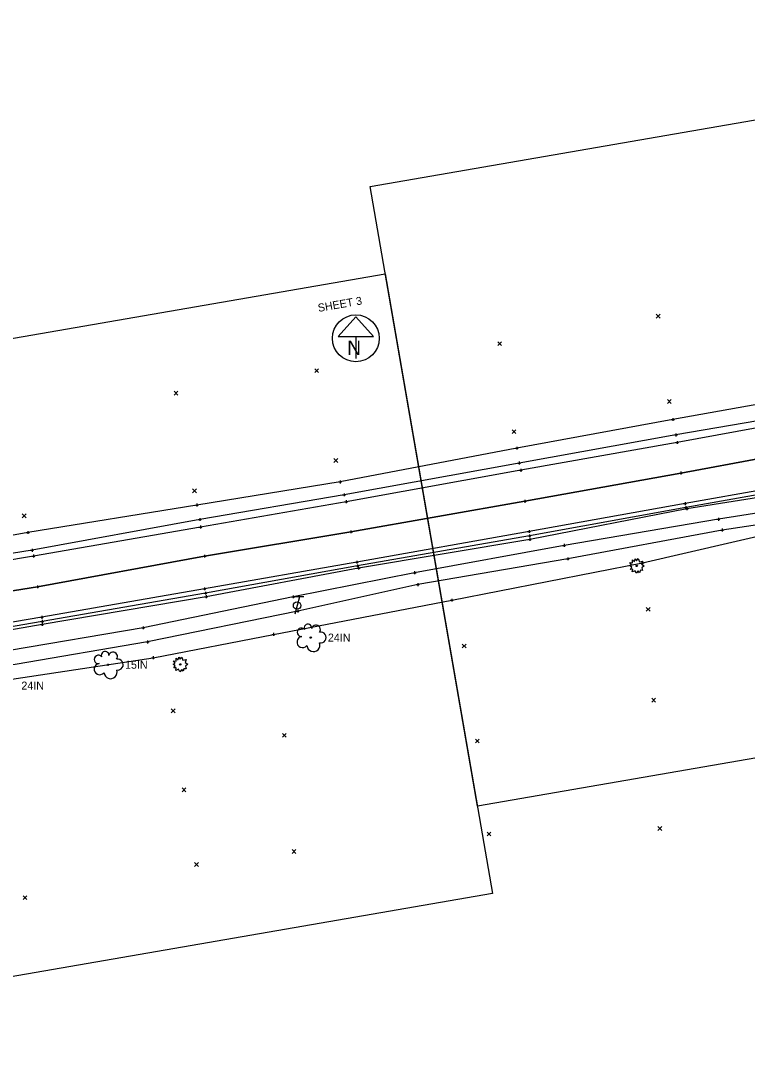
# Model space of a CAD drawing. Extents: x 1386013 to 1389776, y 604170 to 607009.
# Drawn here: x 1387227.5 to 1387481.7, y 604613.9 to 604977.2 of the extents above; entities that cross this region are included whole.
import ezdxf

# ---------------------------------------------------------------- set-up
doc = ezdxf.new("R2010")
doc.units = 0
for name, color, linetype in [('_CIVIL_CONSTRUCTION', 7, 'Continuous'), ('DV_X_Text', 7, 'Continuous'), ('PM_X_CL_Double_Solid', 7, 'Continuous'), ('PV_X_COP', 7, 'Continuous'), ('PV_X_EOP', 7, 'Continuous'), ('PV_X_Shoulder', 7, 'Continuous'), ('SH_Cut_Line', 7, 'Continuous'), ('SH_Masking', 7, 'Continuous'), ('SH_Text', 7, 'Continuous'), ('SV_X_Random_Point', 7, 'Continuous'), ('SV_X_Toe_of_Slope', 7, 'Continuous'), ('SV_X_Top_of_Bank', 7, 'Continuous'), ('UT_X_Telecom_Cells', 7, 'Continuous'), ('VG_X_Text', 7, 'Continuous')]:
    doc.layers.add(name, color=color, linetype=linetype)

msp = doc.modelspace()

# ---------------------------------------------------------------- linework, layer by layer
at = {"layer": '_CIVIL_CONSTRUCTION'}
for points in [[(1387442.96, 604788.25), (1387443.57, 604788.99), (1387443.98, 604787.93), (1387445.08, 604788.11), (1387444.74, 604787.1), (1387445.68, 604786.51), (1387444.83, 604785.77), (1387445.08, 604784.86), (1387444.32, 604784.93), (1387444, 604784.01), (1387443.57, 604784.71), (1387442.89, 604783.89), (1387442.46, 604784.78), (1387441.44, 604784.35), (1387441.63, 604785.29), (1387440.82, 604785.2), (1387441.3, 604785.99), (1387440.53, 604786.56), (1387441.27, 604786.83), (1387440.66, 604787.63), (1387441.59, 604787.52), (1387441.56, 604788.56), (1387442.31, 604787.99), (1387442.52, 604788.97), (1387442.96, 604788.25)], [(1387283.25, 604753.81), (1387283.85, 604754.55), (1387284.27, 604753.49), (1387285.36, 604753.67), (1387285.02, 604752.66), (1387285.97, 604752.07), (1387285.11, 604751.33), (1387285.36, 604750.42), (1387284.61, 604750.49), (1387284.28, 604749.57), (1387283.85, 604750.26), (1387283.18, 604749.45), (1387282.75, 604750.33), (1387281.73, 604749.9), (1387281.92, 604750.85), (1387281.11, 604750.76), (1387281.58, 604751.55), (1387280.81, 604752.12), (1387281.55, 604752.38), (1387280.94, 604753.19), (1387281.88, 604753.08), (1387281.85, 604754.12), (1387282.6, 604753.55), (1387282.81, 604754.53), (1387283.25, 604753.81)]]:
    msp.add_lwpolyline(points, dxfattribs=at)
for centre, radius in [((1387443.05, 604786.44), 0.23), ((1387328.98, 604761.37), 0.24), ((1387257.99, 604751.88), 0.24), ((1387283.33, 604752), 0.23)]:
    msp.add_circle(centre, radius, dxfattribs=at)
for centre, radius, start, end in [((1387327.99, 604764.73), 1.32, 354.0047, 205.9741), ((1387325.67, 604763.23), 1.47, 39.0625, 279.5412), ((1387330.8, 604764.19), 1.55, 323.83, 165.0376), ((1387332.44, 604761.4), 1.91, 259.1453, 101.4596), ((1387326.12, 604759.82), 1.97, 96.1722, 320.5737), ((1387329.92, 604758.76), 2.28, 184.9476, 19.4572), ((1387254.68, 604753.74), 1.47, 39.0625, 279.5412), ((1387257, 604755.25), 1.32, 354.0047, 205.9741), ((1387259.81, 604754.71), 1.55, 323.83, 165.0376), ((1387255.13, 604750.33), 1.97, 96.1722, 320.5737), ((1387261.45, 604751.92), 1.91, 259.1453, 101.4596), ((1387258.93, 604749.27), 2.28, 184.9476, 19.4572)]:
    msp.add_arc(centre, radius, start, end, dxfattribs=at)
at = {"layer": 'DV_X_Text'}
for p, q in [((1387455.23, 604837.69), (1387456.23, 604837.69)), ((1387455.73, 604838.19), (1387455.73, 604837.19)), ((1387455.73, 604837.69), (1387455.73, 604837.69)), ((1387456.28, 604832.26), (1387457.28, 604832.26)), ((1387456.78, 604832.76), (1387456.78, 604831.76)), ((1387456.78, 604832.26), (1387456.78, 604832.26)), ((1387401.04, 604828.15), (1387401.04, 604827.15)), ((1387456.67, 604829.65), (1387457.67, 604829.65)), ((1387457.17, 604830.15), (1387457.17, 604829.15)), ((1387457.17, 604829.65), (1387457.17, 604829.65)), ((1387400.54, 604827.65), (1387401.54, 604827.65)), ((1387401.04, 604827.65), (1387401.04, 604827.65)), ((1387401.41, 604822.43), (1387402.41, 604822.43)), ((1387401.91, 604822.93), (1387401.91, 604821.93)), ((1387401.91, 604822.43), (1387401.91, 604822.43)), ((1387401.94, 604819.9), (1387402.94, 604819.9)), ((1387402.44, 604820.4), (1387402.44, 604819.4)), ((1387402.44, 604819.9), (1387402.44, 604819.9)), ((1387457.99, 604818.93), (1387458.99, 604818.93)), ((1387458.49, 604819.43), (1387458.49, 604818.43)), ((1387458.49, 604818.93), (1387458.49, 604818.93)), ((1387338.79, 604815.83), (1387339.79, 604815.83)), ((1387339.29, 604816.33), (1387339.29, 604815.33)), ((1387339.29, 604815.83), (1387339.29, 604815.83)), ((1387340.13, 604811.34), (1387341.13, 604811.34)), ((1387340.63, 604811.84), (1387340.63, 604810.84)), ((1387340.63, 604811.34), (1387340.63, 604811.34)), ((1387403.9, 604809.55), (1387403.9, 604808.55)), ((1387288.6, 604807.74), (1387289.6, 604807.74)), ((1387289.1, 604808.24), (1387289.1, 604807.24)), ((1387289.1, 604807.74), (1387289.1, 604807.74)), ((1387340.88, 604808.9), (1387341.88, 604808.9)), ((1387341.38, 604809.4), (1387341.38, 604808.4)), ((1387341.38, 604808.9), (1387341.38, 604808.9)), ((1387403.4, 604809.05), (1387404.4, 604809.05)), ((1387403.9, 604809.05), (1387403.9, 604809.05)), ((1387459.46, 604808.24), (1387460.46, 604808.24)), ((1387459.76, 604806.85), (1387460.76, 604806.85)), ((1387459.96, 604808.74), (1387459.96, 604807.74)), ((1387459.96, 604808.24), (1387459.96, 604808.24)), ((1387460.03, 604806.4), (1387461.03, 604806.4)), ((1387460.26, 604807.35), (1387460.26, 604806.35)), ((1387460.26, 604806.85), (1387460.26, 604806.85)), ((1387460.53, 604806.9), (1387460.53, 604805.9)), ((1387460.53, 604806.4), (1387460.53, 604806.4)), ((1387289.61, 604802.67), (1387290.61, 604802.67)), ((1387290.11, 604803.17), (1387290.11, 604802.17)), ((1387290.11, 604802.67), (1387290.11, 604802.67)), ((1387471.12, 604802.75), (1387472.12, 604802.75)), ((1387471.62, 604803.25), (1387471.62, 604802.25)), ((1387471.62, 604802.75), (1387471.62, 604802.75)), ((1387230.03, 604798.65), (1387230.03, 604797.65)), ((1387289.86, 604800.04), (1387290.86, 604800.04)), ((1387290.36, 604800.54), (1387290.36, 604799.54)), ((1387290.36, 604800.04), (1387290.36, 604800.04)), ((1387343.04, 604798.89), (1387343.04, 604797.89)), ((1387405.36, 604799), (1387405.36, 604798)), ((1387472.4, 604799.01), (1387473.4, 604799.01)), ((1387472.9, 604799.51), (1387472.9, 604798.51)), ((1387472.9, 604799.01), (1387472.9, 604799.01)), ((1387229.53, 604798.15), (1387230.53, 604798.15)), ((1387230.03, 604798.15), (1387230.03, 604798.15)), ((1387342.54, 604798.39), (1387343.54, 604798.39)), ((1387343.04, 604798.39), (1387343.04, 604798.39)), ((1387404.86, 604798.5), (1387405.86, 604798.5)), ((1387405.01, 604796.97), (1387406.01, 604796.97)), ((1387405.15, 604795.75), (1387406.15, 604795.75)), ((1387405.36, 604798.5), (1387405.36, 604798.5)), ((1387405.51, 604797.47), (1387405.51, 604796.47)), ((1387405.51, 604796.97), (1387405.51, 604796.97)), ((1387405.65, 604796.25), (1387405.65, 604795.25)), ((1387405.65, 604795.75), (1387405.65, 604795.75)), ((1387230.95, 604791.93), (1387231.95, 604791.93)), ((1387231.45, 604792.43), (1387231.45, 604791.43)), ((1387231.45, 604791.93), (1387231.45, 604791.93)), ((1387417.17, 604793.63), (1387418.17, 604793.63)), ((1387417.67, 604794.13), (1387417.67, 604793.13)), ((1387417.67, 604793.63), (1387417.67, 604793.63)), ((1387231.48, 604789.91), (1387232.48, 604789.91)), ((1387231.98, 604790.41), (1387231.98, 604789.41)), ((1387231.98, 604789.91), (1387231.98, 604789.91)), ((1387291.35, 604789.88), (1387292.35, 604789.88)), ((1387291.85, 604790.38), (1387291.85, 604789.38)), ((1387291.85, 604789.88), (1387291.85, 604789.88)), ((1387344.61, 604787.75), (1387345.61, 604787.75)), ((1387345.11, 604788.25), (1387345.11, 604787.25)), ((1387345.11, 604787.75), (1387345.11, 604787.75)), ((1387418.4, 604788.91), (1387419.4, 604788.91)), ((1387418.9, 604789.41), (1387418.9, 604788.41)), ((1387418.9, 604788.91), (1387418.9, 604788.91)), ((1387445.09, 604788.08), (1387445.09, 604787.08)), ((1387344.82, 604786.5), (1387345.82, 604786.5)), ((1387345.23, 604785.65), (1387346.23, 604785.65)), ((1387345.32, 604787), (1387345.32, 604786)), ((1387345.32, 604786.5), (1387345.32, 604786.5)), ((1387345.73, 604786.15), (1387345.73, 604785.15)), ((1387345.73, 604785.65), (1387345.73, 604785.65)), ((1387365.33, 604784.57), (1387365.33, 604783.57)), ((1387444.59, 604787.58), (1387445.59, 604787.58)), ((1387445.09, 604787.58), (1387445.09, 604787.58)), ((1387364.83, 604784.07), (1387365.83, 604784.07)), ((1387365.33, 604784.07), (1387365.33, 604784.07)), ((1387232.81, 604779.13), (1387233.81, 604779.13)), ((1387233.31, 604779.63), (1387233.31, 604778.63)), ((1387233.31, 604779.13), (1387233.31, 604779.13)), ((1387291.3, 604778.43), (1387292.3, 604778.43)), ((1387291.64, 604776.93), (1387292.64, 604776.93)), ((1387291.8, 604778.93), (1387291.8, 604777.93)), ((1387291.8, 604778.43), (1387291.8, 604778.43)), ((1387292.14, 604777.43), (1387292.14, 604776.43)), ((1387292.14, 604776.93), (1387292.14, 604776.93)), ((1387365.91, 604779.89), (1387366.91, 604779.89)), ((1387366.41, 604780.39), (1387366.41, 604779.39)), ((1387366.41, 604779.89), (1387366.41, 604779.89)), ((1387291.9, 604775.68), (1387292.9, 604775.68)), ((1387292.4, 604776.18), (1387292.4, 604775.18)), ((1387292.4, 604775.68), (1387292.4, 604775.68)), ((1387322.35, 604775.64), (1387323.35, 604775.64)), ((1387322.85, 604776.14), (1387322.85, 604775.14)), ((1387322.85, 604775.64), (1387322.85, 604775.64)), ((1387377.79, 604774.45), (1387378.79, 604774.45)), ((1387378.29, 604774.95), (1387378.29, 604773.95)), ((1387378.29, 604774.45), (1387378.29, 604774.45)), ((1387323.97, 604770.63), (1387324.97, 604770.63)), ((1387324.47, 604771.13), (1387324.47, 604770.13)), ((1387324.47, 604770.63), (1387324.47, 604770.63)), ((1387234.36, 604768.47), (1387235.36, 604768.47)), ((1387234.5, 604765.96), (1387235.5, 604765.96)), ((1387234.54, 604767.03), (1387235.54, 604767.03)), ((1387234.86, 604768.97), (1387234.86, 604767.97)), ((1387234.86, 604768.47), (1387234.86, 604768.47)), ((1387235, 604766.46), (1387235, 604765.46)), ((1387235, 604765.96), (1387235, 604765.96)), ((1387235.04, 604767.53), (1387235.04, 604766.53)), ((1387235.04, 604767.03), (1387235.04, 604767.03)), ((1387269.83, 604764.8), (1387270.83, 604764.8)), ((1387270.33, 604765.3), (1387270.33, 604764.3)), ((1387270.33, 604764.8), (1387270.33, 604764.8)), ((1387315.4, 604762.49), (1387316.4, 604762.49)), ((1387315.9, 604762.99), (1387315.9, 604761.99)), ((1387315.9, 604762.49), (1387315.9, 604762.49)), ((1387271.39, 604759.84), (1387272.39, 604759.84)), ((1387271.89, 604760.34), (1387271.89, 604759.34)), ((1387271.89, 604759.84), (1387271.89, 604759.84)), ((1387273.3, 604754.33), (1387274.3, 604754.33)), ((1387273.8, 604754.83), (1387273.8, 604753.83)), ((1387273.8, 604754.33), (1387273.8, 604754.33))]:
    msp.add_line(p, q, dxfattribs=at)
at = {"layer": 'PM_X_CL_Double_Solid'}
msp.add_lwpolyline([(1386941.92, 604730.57), (1387000.37, 604739.9), (1387059.38, 604750.41), (1387127.32, 604761.93), (1387175.52, 604769.9), (1387233.31, 604779.13), (1387291.85, 604789.88), (1387343.04, 604798.39), (1387403.9, 604809.05), (1387458.49, 604818.93), (1387516.12, 604829.58), (1387574.82, 604839.73), (1387636.99, 604851.11), (1387704.35, 604863.01), (1387787.5, 604877.74), (1387859.73, 604890.76), (1387934.47, 604903.86), (1387998.85, 604914.97), (1388072.27, 604927.44)], dxfattribs=at)
at = {"layer": 'PV_X_COP'}
msp.add_lwpolyline([(1388072.27, 604927.44), (1387998.85, 604914.97), (1387934.47, 604903.86), (1387859.73, 604890.76), (1387787.5, 604877.74), (1387704.35, 604863.01), (1387636.99, 604851.11), (1387574.82, 604839.73), (1387516.12, 604829.58), (1387458.49, 604818.93), (1387403.9, 604809.05), (1387343.04, 604798.39), (1387291.85, 604789.88), (1387233.31, 604779.13), (1387175.52, 604769.9), (1387127.32, 604761.93), (1387059.38, 604750.41), (1387000.37, 604739.9), (1386941.92, 604730.57)], dxfattribs=at)
at = {"layer": 'PV_X_EOP'}
for points in [[(1388070.9, 604937.92), (1387997.67, 604925.46), (1387932.45, 604914.15), (1387857.85, 604900.92), (1387785.1, 604888.09), (1387704.04, 604873.65), (1387634.94, 604861.37), (1387573.23, 604850.33), (1387514.48, 604840.1), (1387457.17, 604829.65), (1387402.44, 604819.9), (1387341.38, 604808.9), (1387290.36, 604800.04), (1387231.98, 604789.91), (1387174.35, 604780.15), (1387125.76, 604771.91), (1387057.82, 604760.3), (1386999.09, 604750.97), (1386941.41, 604741.04)], [(1388073.48, 604916.74), (1388000.2, 604904.18), (1387936.61, 604893.17), (1387861, 604879.89), (1387788.15, 604866.91), (1387706.18, 604852.38), (1387637.62, 604840.16), (1387577.04, 604829.26), (1387518.08, 604818.58), (1387459.96, 604808.24), (1387405.36, 604798.5), (1387345.11, 604787.75), (1387291.8, 604778.43), (1387234.86, 604768.47), (1387177.43, 604758.7), (1387129.4, 604750.56), (1387061.72, 604739.2), (1387002.9, 604729.17), (1386943.42, 604719.4)]]:
    msp.add_lwpolyline(points, dxfattribs=at)
at = {"layer": 'PV_X_Shoulder'}
for points in [[(1388070.88, 604939.75), (1387997.08, 604927.24), (1387932.1, 604916.23), (1387857.34, 604902.99), (1387785.16, 604890.04), (1387703.39, 604875.43), (1387634.35, 604863.66), (1387572.42, 604852.64), (1387514.1, 604842.11), (1387456.78, 604832.26), (1387401.91, 604822.43), (1387340.63, 604811.34), (1387290.11, 604802.67), (1387231.45, 604791.93), (1387174.18, 604782.71), (1387125.33, 604774.1), (1387057.54, 604762.26), (1386998.59, 604752.7), (1386940.97, 604743.32)], [(1388073.66, 604915.38), (1388000.63, 604902.69), (1387936.79, 604891.84), (1387860.98, 604878.42), (1387788.19, 604865.06), (1387706.38, 604850.4), (1387637.88, 604838.5), (1387577.02, 604827.53), (1387518.12, 604817.16), (1387460.26, 604806.85), (1387405.51, 604796.97), (1387345.32, 604786.5), (1387292.14, 604776.93), (1387235.04, 604767.03), (1387177.5, 604757.13), (1387129.28, 604748.59), (1387117.65, 604744.89), (1387099.29, 604741.91), (1387094.7, 604743.05), (1387062.03, 604737.87), (1387002.75, 604727.47), (1386990.61, 604725.25), (1386985.4, 604722.84), (1386965.11, 604719.46)]]:
    msp.add_lwpolyline(points, dxfattribs=at)
at = {"layer": 'SH_Cut_Line'}
for points in [[(1387387.31, 604702.37), (1387349.76, 604919.15), (1387684.77, 604977.18), (1387722.32, 604760.41)], [(1387057.58, 604613.85), (1387020.03, 604830.63), (1387355.04, 604888.66), (1387392.59, 604671.89)]]:
    msp.add_lwpolyline(points, close=True, dxfattribs=at)
at = {"layer": 'SH_Masking'}
msp.add_circle((1387344.77, 604866.09), 8.2, dxfattribs=at)
at = {"layer": 'SH_Text'}
for p, q in [((1387344.77, 604873.57), (1387338.62, 604866.74)), ((1387350.93, 604866.74), (1387344.77, 604873.57)), ((1387338.62, 604866.74), (1387350.93, 604866.74)), ((1387344.77, 604866.74), (1387344.77, 604859.01))]:
    msp.add_line(p, q, dxfattribs=at)
msp.add_circle((1387344.77, 604866.09), 8.2, dxfattribs=at)
at = {"layer": 'SV_X_Random_Point'}
for p, q in [((1387449.88, 604873.17), (1387451.21, 604874.5)), ((1387449.88, 604874.5), (1387451.21, 604873.17)), ((1387394.45, 604863.52), (1387395.78, 604864.85)), ((1387394.45, 604864.85), (1387395.78, 604863.52)), ((1387330.37, 604854.08), (1387331.7, 604855.41)), ((1387330.37, 604855.41), (1387331.7, 604854.08)), ((1387281.13, 604846.22), (1387282.46, 604847.55)), ((1387281.13, 604847.55), (1387282.46, 604846.22)), ((1387453.81, 604843.29), (1387455.15, 604844.63)), ((1387453.81, 604844.63), (1387455.15, 604843.29)), ((1387399.45, 604832.74), (1387400.78, 604834.08)), ((1387399.45, 604834.08), (1387400.78, 604832.74)), ((1387337.1, 604822.67), (1387338.43, 604824)), ((1387337.1, 604824), (1387338.43, 604822.67)), ((1387287.61, 604812.06), (1387288.94, 604813.4)), ((1387287.61, 604813.4), (1387288.94, 604812.06)), ((1387228.04, 604803.3), (1387229.37, 604804.64)), ((1387228.04, 604804.64), (1387229.37, 604803.3)), ((1387446.4, 604770.59), (1387447.74, 604771.93)), ((1387446.4, 604771.93), (1387447.74, 604770.59)), ((1387382.01, 604757.78), (1387383.35, 604759.12)), ((1387382.01, 604759.12), (1387383.35, 604757.78)), ((1387448.31, 604738.8), (1387449.64, 604740.13)), ((1387448.31, 604740.13), (1387449.64, 604738.8)), ((1387280.19, 604735.05), (1387281.52, 604736.39)), ((1387280.19, 604736.39), (1387281.52, 604735.05)), ((1387319.04, 604726.54), (1387320.37, 604727.87)), ((1387319.04, 604727.87), (1387320.37, 604726.54)), ((1387386.57, 604724.53), (1387387.9, 604725.86)), ((1387386.57, 604725.86), (1387387.9, 604724.53)), ((1387283.94, 604707.46), (1387285.27, 604708.8)), ((1387283.94, 604708.8), (1387285.27, 604707.46)), ((1387390.69, 604692), (1387392.03, 604693.33)), ((1387390.69, 604693.33), (1387392.03, 604692)), ((1387450.48, 604693.9), (1387451.81, 604695.23)), ((1387450.48, 604695.23), (1387451.81, 604693.9)), ((1387322.43, 604685.84), (1387323.76, 604687.18)), ((1387322.43, 604687.18), (1387323.76, 604685.84)), ((1387288.35, 604681.33), (1387289.69, 604682.66)), ((1387288.35, 604682.66), (1387289.69, 604681.33)), ((1387228.32, 604669.75), (1387229.65, 604671.08)), ((1387228.32, 604671.08), (1387229.65, 604669.75))]:
    msp.add_line(p, q, dxfattribs=at)
at = {"layer": 'SV_X_Toe_of_Slope'}
for points in [[(1387571.9, 604860.13), (1387513.17, 604847.9), (1387455.73, 604837.69), (1387401.04, 604827.65), (1387339.29, 604815.83), (1387289.1, 604807.74), (1387230.03, 604798.15), (1387173.08, 604787.71), (1387123.84, 604780.19), (1387058.58, 604768.72), (1386997.09, 604757.11), (1386939.93, 604748.73), (1386883.98, 604739), (1386826.09, 604728.82), (1386769.04, 604719.03), (1386711.7, 604710.77), (1386654.03, 604700.72), (1386592.6, 604690.63), (1386534.1, 604681.18), (1386480.03, 604672.89), (1386465.51, 604671.66), (1386391.46, 604656.56), (1386330.8, 604647.36), (1386266.18, 604637.16)], [(1387642.64, 604832.21), (1387598.48, 604823.3), (1387558.95, 604817.37), (1387510.99, 604808.94), (1387471.62, 604802.75), (1387417.67, 604793.63), (1387365.33, 604784.07), (1387322.85, 604775.64), (1387270.33, 604764.8), (1387223.53, 604756.91), (1387181.6, 604750.67), (1387155.52, 604744), (1387129.15, 604740.81), (1387125.03, 604741.78), (1387120.43, 604741.02)], [(1387645.49, 604830.06), (1387640.63, 604828.81), (1387599.43, 604819.65), (1387560.44, 604813.11), (1387511.64, 604804.79), (1387472.9, 604799.01), (1387418.9, 604788.91), (1387366.41, 604779.89), (1387324.47, 604770.63), (1387271.89, 604759.84), (1387225.55, 604751.97), (1387182.66, 604746.29), (1387156.28, 604739.69), (1387120.85, 604736.53)]]:
    msp.add_lwpolyline(points, dxfattribs=at)
at = {"layer": 'SV_X_Top_of_Bank'}
for points in [[(1387579.31, 604826.78), (1387518.18, 604816.16), (1387495.21, 604811.9), (1387460.53, 604806.4), (1387405.65, 604795.75), (1387345.73, 604785.65), (1387292.4, 604775.68), (1387235, 604765.96), (1387177.62, 604755.88), (1387129.66, 604747.3), (1387125.36, 604745.57), (1387119.56, 604742.59), (1387120.12, 604734.17)], [(1387120.44, 604732.56), (1387162.47, 604738.46), (1387215.74, 604745.53), (1387273.8, 604754.33), (1387315.9, 604762.49), (1387378.29, 604774.45), (1387445.09, 604787.58), (1387492, 604798.41), (1387538.69, 604807.91), (1387587.5, 604815.89), (1387625.32, 604823.63), (1387642.48, 604825.61)]]:
    msp.add_lwpolyline(points, dxfattribs=at)
at = {"layer": 'UT_X_Telecom_Cells'}
for p, q in [((1387326.59, 604775.58), (1387323.39, 604775.58)), ((1387324.99, 604775.58), (1387323.39, 604769.58))]:
    msp.add_line(p, q, dxfattribs=at)
msp.add_circle((1387324.19, 604772.58), 1.3, dxfattribs=at)

# ---------------------------------------------------------------- texts
at = {"layer": 'SH_Text'}
msp.add_text('SHEET 3', height=2.8, rotation=9.8279, dxfattribs=at).set_placement((1387331.72, 604875.3))
msp.add_text('N', height=5, dxfattribs=at).set_placement((1387341.75, 604860.27))
at = {"layer": 'VG_X_Text'}
for s, p in [('24IN', (1387334.98, 604759.97)), ('15IN', (1387263.99, 604750.48)), ('24IN', (1387227.72, 604743.18))]:
    msp.add_text(s, height=2.8, dxfattribs=at).set_placement(p)

doc.saveas('drawing.dxf')
